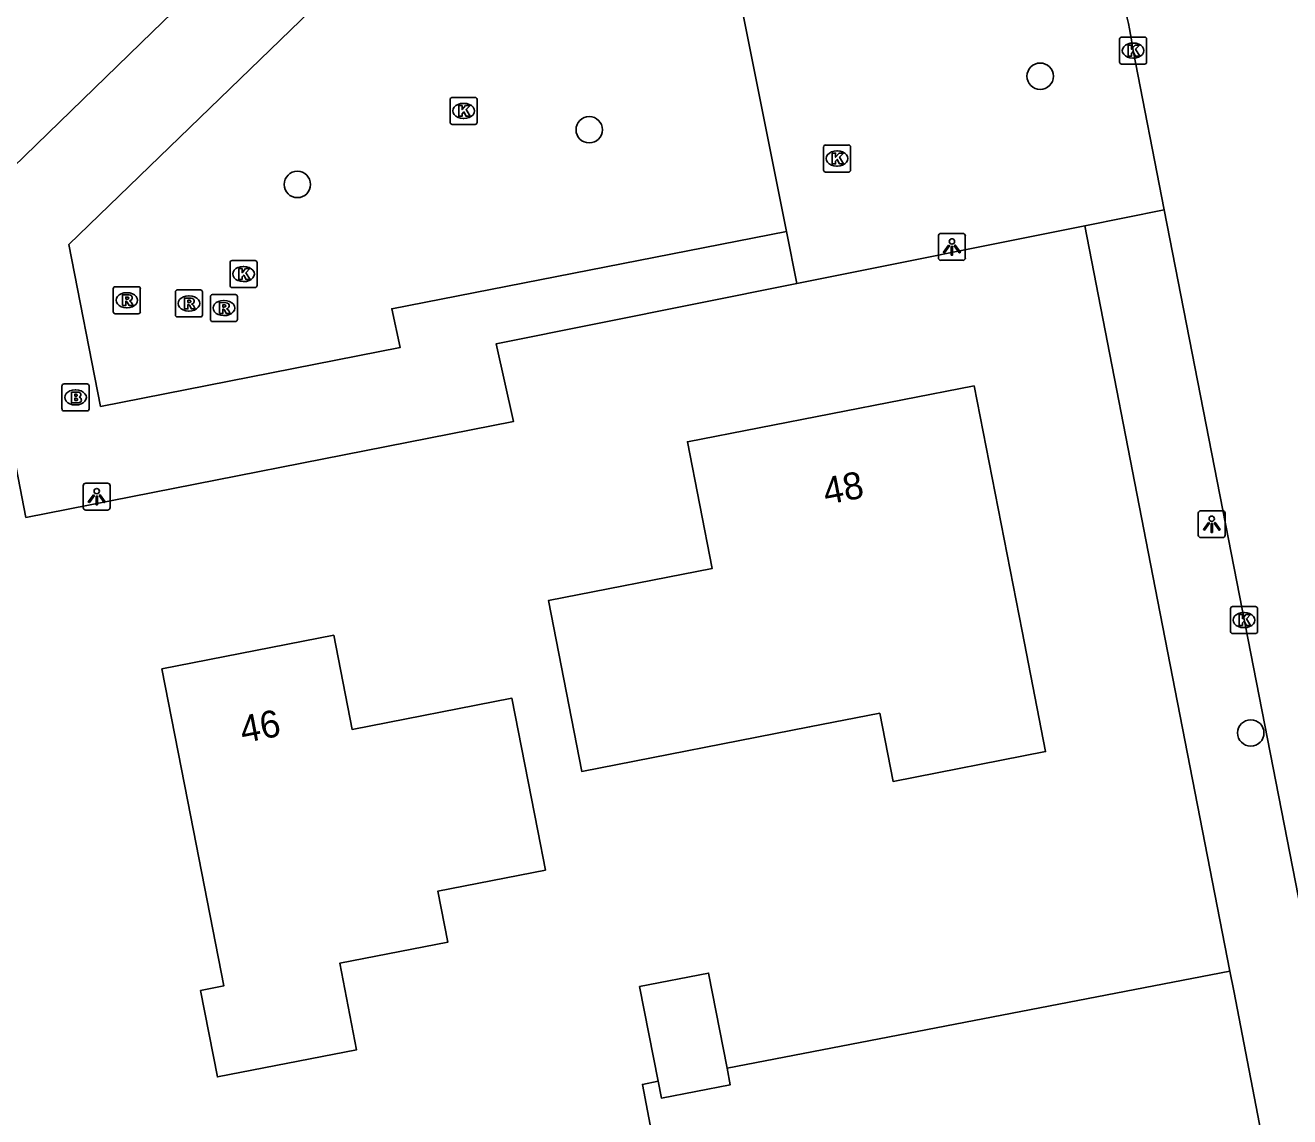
# Model space of a CAD drawing. Extents: x 157663 to 158496, y 379212 to 380934.
# Drawn here: x 158087.14 to 158133.99, y 380307.81 to 380348.23 of the extents above; entities that cross this region are included whole.
import ezdxf

# ---------------------------------------------------------------- set-up
doc = ezdxf.new("R2010")
doc.units = 0
for name, color, linetype in [('IMGEO_Boom', 7, 'Continuous'), ('IMGEO_Brandkraan', 7, 'Continuous'), ('IMGEO_Groenvoorziening', 7, 'Continuous'), ('IMGEO_Kolk', 7, 'Continuous'), ('IMGEO_Lichtpunt', 7, 'Continuous'), ('IMGEO_Muur', 7, 'Continuous'), ('IMGEO_Pand', 7, 'Continuous'), ('IMGEO_Pand_nummerreeks', 7, 'Continuous'), ('IMGEO_Rijbaan_lokaal_open', 7, 'Continuous'), ('IMGEO_Rioolput', 7, 'Continuous'), ('IMGEO_Voetpad_open', 7, 'Continuous')]:
    doc.layers.add(name, color=color, linetype=linetype)

msp = doc.modelspace()

# ---------------------------------------------------------------- linework, layer by layer
at = {"layer": 'IMGEO_Boom'}
for centre in [(158124.745, 380346.342), (158108.037, 380344.362), (158097.224, 380342.336), (158132.548, 380322.021)]:
    msp.add_circle(centre, 0.489, dxfattribs=at)
at = {"layer": 'IMGEO_Brandkraan'}
for p, q in [((158088.504, 380334.022), (158088.504, 380334.874)), ((158088.579, 380334.948), (158089.431, 380334.948)), ((158089.505, 380334.874), (158089.505, 380334.022)), ((158088.992, 380334.728), (158089.017, 380334.728)), ((158089.431, 380333.948), (158088.579, 380333.948)), ((158089.015, 380334.168), (158088.99, 380334.168))]:
    msp.add_line(p, q, dxfattribs=at)
for points in [[(158088.504, 380334.022), (158088.504, 380334.874)], [(158088.579, 380334.948), (158089.431, 380334.948)], [(158089.505, 380334.874), (158089.505, 380334.022)], [(158088.852, 380334.648), (158088.852, 380334.248), (158089.065, 380334.248)], [(158089.083, 380334.648), (158088.852, 380334.648)], [(158089.031, 380334.567), (158088.977, 380334.567), (158088.977, 380334.491)], [(158088.977, 380334.491), (158089.03, 380334.491)], [(158089.039, 380334.415), (158088.977, 380334.415), (158088.977, 380334.334)], [(158088.977, 380334.334), (158089.039, 380334.334)], [(158089.431, 380333.948), (158088.579, 380333.948)]]:
    msp.add_lwpolyline(points, dxfattribs=at)
for centre, radius, start, end in [((158088.581, 380334.872), 0.0765, 91.552, 178.448), ((158088.581, 380334.872), 0.0765, 91.552, 178.448), ((158089.429, 380334.872), 0.0765, 1.552, 88.448), ((158089.429, 380334.872), 0.0765, 1.552, 88.448), ((158089.032, 380334.529), 0.0379, 267.8285, 90.9355), ((158089.04, 380334.374), 0.0404, 269.8759, 90.5077), ((158089.087, 380334.503), 0.145, 59.4692, 91.5367), ((158089.112, 380334.55), 0.0922, 285.5137, 58.1501), ((158089.117, 380334.358), 0.105, 301.3115, 78.989), ((158088.581, 380334.024), 0.0765, 181.552, 268.448), ((158088.581, 380334.024), 0.0765, 181.552, 268.448), ((158089.071, 380334.499), 0.251, 268.6676, 293.5347), ((158089.429, 380334.024), 0.0765, 271.552, 358.448), ((158089.429, 380334.024), 0.0765, 271.552, 358.448)]:
    msp.add_arc(centre, radius, start, end, dxfattribs=at)
for centre, major_axis, ratio, start_param, end_param in [((158088.991, 380334.448), (-0.387, 0.002), 0.722429, 4.712389, 7.853982), ((158089.016, 380334.448), (-0.39, 0.002), 0.717154, 1.570796, 4.712389)]:
    msp.add_ellipse(centre, major_axis=major_axis, ratio=ratio, start_param=start_param, end_param=end_param, dxfattribs=at)
at = {"layer": 'IMGEO_Groenvoorziening'}
for points in [[(158113.145, 380309.614), (158131.772, 380313.203)], [(158096.749, 380300.843), (158111.034, 380303.611), (158110.006, 380309.009), (158110.588, 380309.121)]]:
    msp.add_lwpolyline(points, dxfattribs=at)
at = {"layer": 'IMGEO_Kolk'}
for p, q in [((158127.688, 380346.866), (158127.688, 380347.718)), ((158127.763, 380347.792), (158128.615, 380347.792)), ((158128.176, 380347.572), (158128.201, 380347.572)), ((158128.689, 380347.718), (158128.689, 380346.866)), ((158128.199, 380347.012), (158128.174, 380347.012)), ((158128.615, 380346.792), (158127.763, 380346.792)), ((158102.884, 380344.632), (158102.884, 380345.484)), ((158102.959, 380345.558), (158103.811, 380345.558)), ((158103.372, 380345.338), (158103.397, 380345.338)), ((158103.885, 380345.484), (158103.885, 380344.632)), ((158103.395, 380344.778), (158103.37, 380344.778)), ((158103.811, 380344.558), (158102.959, 380344.558)), ((158116.719, 380342.87), (158116.719, 380343.722)), ((158116.794, 380343.796), (158117.646, 380343.796)), ((158117.72, 380343.722), (158117.72, 380342.87)), ((158117.207, 380343.576), (158117.232, 380343.576)), ((158117.646, 380342.796), (158116.794, 380342.796)), ((158117.23, 380343.016), (158117.205, 380343.016)), ((158094.804, 380339.517), (158095.656, 380339.517)), ((158094.729, 380338.591), (158094.729, 380339.443)), ((158095.217, 380339.297), (158095.242, 380339.297)), ((158095.73, 380339.443), (158095.73, 380338.591)), ((158095.24, 380338.737), (158095.215, 380338.737)), ((158095.656, 380338.517), (158094.804, 380338.517)), ((158131.796, 380325.777), (158131.796, 380326.629)), ((158131.871, 380326.703), (158132.723, 380326.703)), ((158132.284, 380326.483), (158132.309, 380326.483)), ((158132.797, 380326.629), (158132.797, 380325.777)), ((158132.307, 380325.923), (158132.282, 380325.923)), ((158132.723, 380325.703), (158131.871, 380325.703))]:
    msp.add_line(p, q, dxfattribs=at)
for points in [[(158127.688, 380346.866), (158127.688, 380347.718)], [(158127.763, 380347.792), (158128.615, 380347.792)], [(158128.009, 380347.492), (158128.132, 380347.492), (158128.132, 380347.341), (158128.262, 380347.492), (158128.426, 380347.492), (158128.28, 380347.341), (158128.433, 380347.092), (158128.281, 380347.092), (158128.196, 380347.256), (158128.132, 380347.189), (158128.132, 380347.092), (158128.009, 380347.092), (158128.009, 380347.492)], [(158128.689, 380347.718), (158128.689, 380346.866)], [(158128.615, 380346.792), (158127.763, 380346.792)], [(158102.884, 380344.632), (158102.884, 380345.484)], [(158102.959, 380345.558), (158103.811, 380345.558)], [(158103.205, 380345.258), (158103.328, 380345.258), (158103.328, 380345.107), (158103.458, 380345.258), (158103.622, 380345.258), (158103.476, 380345.107), (158103.629, 380344.858), (158103.477, 380344.858), (158103.392, 380345.022), (158103.328, 380344.955), (158103.328, 380344.858), (158103.205, 380344.858), (158103.205, 380345.258)], [(158103.885, 380345.484), (158103.885, 380344.632)], [(158103.811, 380344.558), (158102.959, 380344.558)], [(158116.719, 380342.87), (158116.719, 380343.722)], [(158116.794, 380343.796), (158117.646, 380343.796)], [(158117.72, 380343.722), (158117.72, 380342.87)], [(158117.04, 380343.496), (158117.163, 380343.496), (158117.163, 380343.345), (158117.293, 380343.496), (158117.457, 380343.496), (158117.311, 380343.345), (158117.464, 380343.096), (158117.312, 380343.096), (158117.227, 380343.26), (158117.163, 380343.193), (158117.163, 380343.096), (158117.04, 380343.096), (158117.04, 380343.496)], [(158117.646, 380342.796), (158116.794, 380342.796)], [(158094.804, 380339.517), (158095.656, 380339.517)], [(158094.729, 380338.591), (158094.729, 380339.443)], [(158095.05, 380339.217), (158095.173, 380339.217), (158095.173, 380339.066), (158095.303, 380339.217), (158095.467, 380339.217), (158095.321, 380339.066), (158095.474, 380338.817), (158095.322, 380338.817), (158095.237, 380338.981), (158095.173, 380338.914), (158095.173, 380338.817), (158095.05, 380338.817), (158095.05, 380339.217)], [(158095.73, 380339.443), (158095.73, 380338.591)], [(158095.656, 380338.517), (158094.804, 380338.517)], [(158131.796, 380325.777), (158131.796, 380326.629)], [(158131.871, 380326.703), (158132.723, 380326.703)], [(158132.117, 380326.403), (158132.24, 380326.403), (158132.24, 380326.252), (158132.37, 380326.403), (158132.534, 380326.403), (158132.388, 380326.252), (158132.541, 380326.003), (158132.389, 380326.003), (158132.304, 380326.167), (158132.24, 380326.1), (158132.24, 380326.003), (158132.117, 380326.003), (158132.117, 380326.403)], [(158132.797, 380326.629), (158132.797, 380325.777)], [(158132.723, 380325.703), (158131.871, 380325.703)]]:
    msp.add_lwpolyline(points, dxfattribs=at)
for centre, start, end in [((158127.765, 380347.716), 91.552, 178.448), ((158127.765, 380347.716), 91.552, 178.448), ((158128.613, 380347.716), 1.552, 88.448), ((158128.613, 380347.716), 1.552, 88.448), ((158127.765, 380346.868), 181.552, 268.448), ((158127.765, 380346.868), 181.552, 268.448), ((158128.613, 380346.868), 271.552, 358.448), ((158128.613, 380346.868), 271.552, 358.448), ((158102.961, 380345.482), 91.552, 178.448), ((158102.961, 380345.482), 91.552, 178.448), ((158103.809, 380345.482), 1.552, 88.448), ((158103.809, 380345.482), 1.552, 88.448), ((158102.961, 380344.634), 181.552, 268.448), ((158102.961, 380344.634), 181.552, 268.448), ((158103.809, 380344.634), 271.552, 358.448), ((158103.809, 380344.634), 271.552, 358.448), ((158116.796, 380343.72), 91.552, 178.448), ((158116.796, 380343.72), 91.552, 178.448), ((158117.644, 380343.72), 1.552, 88.448), ((158117.644, 380343.72), 1.552, 88.448), ((158116.796, 380342.872), 181.552, 268.448), ((158116.796, 380342.872), 181.552, 268.448), ((158117.644, 380342.872), 271.552, 358.448), ((158117.644, 380342.872), 271.552, 358.448), ((158094.806, 380339.441), 91.552, 178.448), ((158094.806, 380339.441), 91.552, 178.448), ((158095.654, 380339.441), 1.552, 88.448), ((158095.654, 380339.441), 1.552, 88.448), ((158094.806, 380338.593), 181.552, 268.448), ((158094.806, 380338.593), 181.552, 268.448), ((158095.654, 380338.593), 271.552, 358.448), ((158095.654, 380338.593), 271.552, 358.448), ((158131.873, 380326.627), 91.552, 178.448), ((158131.873, 380326.627), 91.552, 178.448), ((158132.721, 380326.627), 1.552, 88.448), ((158132.721, 380326.627), 1.552, 88.448), ((158131.873, 380325.779), 181.552, 268.448), ((158131.873, 380325.779), 181.552, 268.448), ((158132.721, 380325.779), 271.552, 358.448), ((158132.721, 380325.779), 271.552, 358.448)]:
    msp.add_arc(centre, 0.0765, start, end, dxfattribs=at)
for centre, major_axis, ratio, start_param, end_param in [((158128.175, 380347.292), (-0.387, 0.002), 0.722429, 4.712389, 7.853982), ((158128.2, 380347.292), (-0.39, 0.002), 0.717154, 1.570796, 4.712389), ((158103.371, 380345.058), (-0.387, 0.002), 0.722429, 4.712389, 7.853982), ((158103.396, 380345.058), (-0.39, 0.002), 0.717154, 1.570796, 4.712389), ((158117.206, 380343.296), (-0.387, 0.002), 0.722429, 4.712389, 7.853982), ((158117.231, 380343.296), (-0.39, 0.002), 0.717154, 1.570796, 4.712389), ((158095.216, 380339.017), (-0.387, 0.002), 0.722429, 4.712389, 7.853982), ((158095.241, 380339.017), (-0.39, 0.002), 0.717154, 1.570796, 4.712389), ((158132.283, 380326.203), (-0.387, 0.002), 0.722429, 4.712389, 7.853982), ((158132.308, 380326.203), (-0.39, 0.002), 0.717154, 1.570796, 4.712389)]:
    msp.add_ellipse(centre, major_axis=major_axis, ratio=ratio, start_param=start_param, end_param=end_param, dxfattribs=at)
at = {"layer": 'IMGEO_Lichtpunt'}
for p, q in [((158120.976, 380340.426), (158120.976, 380339.619)), ((158120.976, 380340.426), (158120.976, 380339.619)), ((158121.878, 380340.521), (158121.07, 380340.521)), ((158121.878, 380340.521), (158121.07, 380340.521)), ((158121.972, 380339.619), (158121.972, 380340.426)), ((158121.972, 380339.619), (158121.972, 380340.426)), ((158121.07, 380339.525), (158121.878, 380339.525)), ((158121.07, 380339.525), (158121.878, 380339.525)), ((158089.292, 380331.178), (158089.292, 380330.371)), ((158089.292, 380331.178), (158089.292, 380330.371)), ((158090.194, 380331.273), (158089.386, 380331.273)), ((158090.194, 380331.273), (158089.386, 380331.273)), ((158090.288, 380330.371), (158090.288, 380331.178)), ((158090.288, 380330.371), (158090.288, 380331.178)), ((158089.386, 380330.277), (158090.194, 380330.277)), ((158089.386, 380330.277), (158090.194, 380330.277)), ((158130.603, 380330.157), (158130.603, 380329.35)), ((158130.603, 380330.157), (158130.603, 380329.35)), ((158131.505, 380330.252), (158130.697, 380330.252)), ((158131.505, 380330.252), (158130.697, 380330.252)), ((158131.599, 380329.35), (158131.599, 380330.157)), ((158131.599, 380329.35), (158131.599, 380330.157)), ((158130.697, 380329.256), (158131.505, 380329.256)), ((158130.697, 380329.256), (158131.505, 380329.256))]:
    msp.add_line(p, q, dxfattribs=at)
for points in [[(158121.35, 380340.09), (158121.389, 380340.062), (158121.201, 380339.8), (158121.163, 380339.827), (158121.35, 380340.09)], [(158121.452, 380340.042), (158121.499, 380340.042), (158121.499, 380339.72), (158121.452, 380339.72), (158121.452, 380340.042)], [(158121.562, 380340.062), (158121.6, 380340.089), (158121.787, 380339.827), (158121.748, 380339.799), (158121.562, 380340.062)], [(158089.666, 380330.842), (158089.705, 380330.814), (158089.517, 380330.552), (158089.479, 380330.579), (158089.666, 380330.842)], [(158089.768, 380330.794), (158089.815, 380330.794), (158089.815, 380330.472), (158089.768, 380330.472), (158089.768, 380330.794)], [(158089.878, 380330.814), (158089.916, 380330.841), (158090.103, 380330.579), (158090.064, 380330.551), (158089.878, 380330.814)], [(158130.977, 380329.821), (158131.016, 380329.793), (158130.828, 380329.531), (158130.79, 380329.558), (158130.977, 380329.821)], [(158131.079, 380329.773), (158131.126, 380329.773), (158131.126, 380329.451), (158131.079, 380329.451), (158131.079, 380329.773)], [(158131.189, 380329.793), (158131.227, 380329.82), (158131.414, 380329.558), (158131.375, 380329.53), (158131.189, 380329.793)]]:
    msp.add_lwpolyline(points, dxfattribs=at)
for centre in [(158121.475, 380340.224), (158089.791, 380330.976), (158131.102, 380329.955)]:
    msp.add_circle(centre, 0.0994, dxfattribs=at)
for centre, start, end in [((158121.07, 380340.426), 90, 180), ((158121.07, 380340.426), 90, 180), ((158121.878, 380340.426), 0, 90), ((158121.878, 380340.426), 0, 90), ((158121.07, 380339.619), 180, 270), ((158121.07, 380339.619), 180, 270), ((158121.878, 380339.619), 270, 0), ((158121.878, 380339.619), 270, 360), ((158089.386, 380331.178), 90, 180), ((158089.386, 380331.178), 90, 180), ((158090.194, 380331.178), 0, 90), ((158090.194, 380331.178), 0, 90), ((158089.386, 380330.371), 180, 270), ((158089.386, 380330.371), 180, 270), ((158090.194, 380330.371), 270, 0), ((158090.194, 380330.371), 270, 360), ((158130.697, 380330.157), 90, 180), ((158130.697, 380330.157), 90, 180), ((158131.505, 380330.157), 0, 90), ((158131.505, 380330.157), 0, 90), ((158130.697, 380329.35), 180, 270), ((158130.697, 380329.35), 180, 270), ((158131.505, 380329.35), 270, 0), ((158131.505, 380329.35), 270, 360)]:
    msp.add_arc(centre, 0.0946, start, end, dxfattribs=at)
at = {"layer": 'IMGEO_Muur'}
for points in [[(158131.772, 380313.203), (158129.007, 380327.399)], [(158131.914, 380312.475), (158131.772, 380313.203)]]:
    msp.add_lwpolyline(points, dxfattribs=at)
at = {"layer": 'IMGEO_Pand'}
for points in [[(158122.301, 380334.88), (158124.076, 380325.792), (158124.947, 380321.33), (158119.293, 380320.226), (158118.799, 380322.755), (158116.199, 380322.247), (158107.759, 380320.598), (158106.524, 380326.926), (158112.591, 380328.111), (158111.674, 380332.805), (158122.301, 380334.88)], [(158098.572, 380325.64), (158099.253, 380322.154), (158105.173, 380323.31), (158106.131, 380318.403), (158106.416, 380316.946), (158102.43, 380316.168), (158102.799, 380314.274), (158098.793, 380313.491), (158099.418, 380310.29), (158094.262, 380309.283), (158093.637, 380312.484), (158094.497, 380312.652), (158093.162, 380319.489), (158092.203, 380324.396), (158098.572, 380325.64)], [(158110.588, 380309.121), (158109.902, 380312.632), (158112.458, 380313.131), (158113.145, 380309.614)], [(158113.145, 380309.614), (158113.265, 380308.997), (158110.71, 380308.498), (158110.588, 380309.121)]]:
    msp.add_lwpolyline(points, dxfattribs=at)
at = {"layer": 'IMGEO_Rijbaan_lokaal_open'}
for points in [[(158128.189, 380347.292), (158129.341, 380341.394)], [(158136.427, 380304.445), (158136.397, 380304.765), (158135.855, 380308.031), (158129.341, 380341.394)]]:
    msp.add_lwpolyline(points, dxfattribs=at)
msp.add_arc((158103.173, 380343.419), 25.314, 8.7999, 16.1583, dxfattribs=at)
at = {"layer": 'IMGEO_Rioolput'}
for p, q in [((158090.48, 380338.547), (158091.332, 380338.547)), ((158090.405, 380337.621), (158090.405, 380338.473)), ((158090.893, 380338.327), (158090.918, 380338.327)), ((158091.406, 380338.473), (158091.406, 380337.621)), ((158092.706, 380337.501), (158092.706, 380338.353)), ((158092.781, 380338.427), (158093.633, 380338.427)), ((158093.194, 380338.207), (158093.219, 380338.207)), ((158093.707, 380338.353), (158093.707, 380337.501)), ((158094.002, 380337.332), (158094.002, 380338.184)), ((158094.077, 380338.258), (158094.929, 380338.258)), ((158095.003, 380338.184), (158095.003, 380337.332)), ((158090.916, 380337.767), (158090.891, 380337.767)), ((158093.217, 380337.647), (158093.192, 380337.647)), ((158094.49, 380338.038), (158094.515, 380338.038)), ((158091.332, 380337.547), (158090.48, 380337.547)), ((158093.633, 380337.427), (158092.781, 380337.427)), ((158094.929, 380337.258), (158094.077, 380337.258)), ((158094.513, 380337.478), (158094.488, 380337.478))]:
    msp.add_line(p, q, dxfattribs=at)
for points in [[(158090.48, 380338.547), (158091.332, 380338.547)], [(158090.405, 380337.621), (158090.405, 380338.473)], [(158090.994, 380338.245), (158090.742, 380338.247), (158090.742, 380337.847)], [(158090.92, 380338.166), (158090.866, 380338.166), (158090.866, 380338.085)], [(158090.866, 380338.085), (158090.918, 380338.085)], [(158091.406, 380338.473), (158091.406, 380337.621)], [(158092.706, 380337.501), (158092.706, 380338.353)], [(158092.781, 380338.427), (158093.633, 380338.427)], [(158093.295, 380338.125), (158093.043, 380338.127), (158093.043, 380337.727)], [(158093.707, 380338.353), (158093.707, 380337.501)], [(158094.002, 380337.332), (158094.002, 380338.184)], [(158094.077, 380338.258), (158094.929, 380338.258)], [(158095.003, 380338.184), (158095.003, 380337.332)], [(158090.742, 380337.847), (158090.866, 380337.847), (158090.866, 380338.009), (158090.877, 380338.009)], [(158090.924, 380337.98), (158090.995, 380337.847), (158091.135, 380337.847), (158091.07, 380337.973)], [(158093.043, 380337.727), (158093.167, 380337.727), (158093.167, 380337.889), (158093.178, 380337.889)], [(158093.221, 380338.046), (158093.167, 380338.046), (158093.167, 380337.965)], [(158093.167, 380337.965), (158093.219, 380337.965)], [(158093.225, 380337.86), (158093.296, 380337.727), (158093.436, 380337.727), (158093.371, 380337.853)], [(158094.591, 380337.956), (158094.339, 380337.958), (158094.339, 380337.558)], [(158094.339, 380337.558), (158094.463, 380337.558), (158094.463, 380337.72), (158094.474, 380337.72)], [(158094.517, 380337.877), (158094.463, 380337.877), (158094.463, 380337.796)], [(158094.463, 380337.796), (158094.515, 380337.796)], [(158094.521, 380337.691), (158094.592, 380337.558), (158094.732, 380337.558), (158094.667, 380337.684)], [(158091.332, 380337.547), (158090.48, 380337.547)], [(158093.633, 380337.427), (158092.781, 380337.427)], [(158094.929, 380337.258), (158094.077, 380337.258)]]:
    msp.add_lwpolyline(points, dxfattribs=at)
for centre, radius, start, end in [((158090.482, 380338.471), 0.0765, 91.552, 178.448), ((158090.482, 380338.471), 0.0765, 91.552, 178.448), ((158091.33, 380338.471), 0.0765, 1.552, 88.448), ((158091.33, 380338.471), 0.0765, 1.552, 88.448), ((158090.902, 380338.274), 0.19, 274.7715, 282.9687), ((158090.926, 380338.07), 0.0964, 77.0061, 93.1865), ((158090.94, 380338.127), 0.0378, 276.6634, 79.6772), ((158090.993, 380338.135), 0.109, 350.3612, 89.416), ((158090.991, 380338.135), 0.112, 277.5842, 350.9817), ((158092.783, 380338.351), 0.0765, 91.552, 178.448), ((158092.783, 380338.351), 0.0765, 91.552, 178.448), ((158093.294, 380338.015), 0.109, 350.3612, 89.416), ((158093.631, 380338.351), 0.0765, 1.552, 88.448), ((158093.631, 380338.351), 0.0765, 1.552, 88.448), ((158094.079, 380338.182), 0.0765, 91.552, 178.448), ((158094.079, 380338.182), 0.0765, 91.552, 178.448), ((158094.927, 380338.182), 0.0765, 1.552, 88.448), ((158094.927, 380338.182), 0.0765, 1.552, 88.448), ((158090.482, 380337.623), 0.0765, 181.552, 268.448), ((158090.482, 380337.623), 0.0765, 181.552, 268.448), ((158090.876, 380337.956), 0.0533, 26.0293, 88.6989), ((158090.975, 380337.92), 0.108, 29.5134, 73.7905), ((158091.33, 380337.623), 0.0765, 271.552, 358.448), ((158091.33, 380337.623), 0.0765, 271.552, 358.448), ((158093.177, 380337.836), 0.0533, 26.0293, 88.6989), ((158093.203, 380338.154), 0.19, 274.7715, 282.9687), ((158093.227, 380337.95), 0.0964, 77.0061, 93.1865), ((158093.241, 380338.007), 0.0378, 276.6634, 79.6772), ((158093.292, 380338.015), 0.112, 277.5842, 350.9817), ((158093.276, 380337.8), 0.108, 29.5134, 73.7905), ((158094.473, 380337.667), 0.0533, 26.0293, 88.6989), ((158094.499, 380337.985), 0.19, 274.7715, 282.9687), ((158094.523, 380337.781), 0.0964, 77.0061, 93.1865), ((158094.537, 380337.838), 0.0378, 276.6634, 79.6772), ((158094.59, 380337.846), 0.109, 350.3612, 89.416), ((158094.588, 380337.846), 0.112, 277.5842, 350.9817), ((158094.572, 380337.631), 0.108, 29.5134, 73.7905), ((158092.783, 380337.503), 0.0765, 181.552, 268.448), ((158092.783, 380337.503), 0.0765, 181.552, 268.448), ((158093.631, 380337.503), 0.0765, 271.552, 358.448), ((158093.631, 380337.503), 0.0765, 271.552, 358.448), ((158094.079, 380337.334), 0.0765, 181.552, 268.448), ((158094.079, 380337.334), 0.0765, 181.552, 268.448), ((158094.927, 380337.334), 0.0765, 271.552, 358.448), ((158094.927, 380337.334), 0.0765, 271.552, 358.448)]:
    msp.add_arc(centre, radius, start, end, dxfattribs=at)
for centre, major_axis, ratio, start_param, end_param in [((158090.892, 380338.047), (-0.387, 0.002), 0.722429, 4.712389, 7.853982), ((158090.917, 380338.047), (-0.39, 0.002), 0.717154, 1.570796, 4.712389), ((158093.193, 380337.927), (-0.387, 0.002), 0.722429, 4.712389, 7.853982), ((158093.218, 380337.927), (-0.39, 0.002), 0.717154, 1.570796, 4.712389), ((158094.489, 380337.758), (-0.387, 0.002), 0.722429, 4.712389, 7.853982), ((158094.514, 380337.758), (-0.39, 0.002), 0.717154, 1.570796, 4.712389)]:
    msp.add_ellipse(centre, major_axis=major_axis, ratio=ratio, start_param=start_param, end_param=end_param, dxfattribs=at)
at = {"layer": 'IMGEO_Voetpad_open'}
for points in [[(158115.735, 380338.668), (158104.594, 380336.436), (158105.235, 380333.559), (158087.167, 380330.005), (158084.961, 380341.306), (158091.847, 380347.972), (158100.664, 380356.509), (158103.667, 380359.403), (158105.995, 380361.632)], [(158115.35, 380340.589), (158100.719, 380337.733), (158101.038, 380336.301), (158089.931, 380334.116), (158088.76, 380340.112), (158106.293, 380357.072)], [(158115.35, 380340.589), (158113.553, 380349.557), (158106.293, 380357.072)], [(158129.341, 380341.394), (158126.396, 380340.804)], [(158115.735, 380338.668), (158115.35, 380340.589)], [(158126.396, 380340.804), (158115.735, 380338.668)], [(158131.772, 380313.203), (158129.007, 380327.399), (158126.396, 380340.804)], [(158133.177, 380305.934), (158131.914, 380312.475), (158131.772, 380313.203)]]:
    msp.add_lwpolyline(points, dxfattribs=at)

# ---------------------------------------------------------------- texts
at = {"layer": 'IMGEO_Pand_nummerreeks'}
for s, rotation, p in [('48', 11.0466, (158116.808, 380330.466)), ('46', 11.0524, (158095.205, 380321.641))]:
    msp.add_text(s, height=1, rotation=rotation, dxfattribs=at).set_placement(p)

doc.saveas('drawing.dxf')
